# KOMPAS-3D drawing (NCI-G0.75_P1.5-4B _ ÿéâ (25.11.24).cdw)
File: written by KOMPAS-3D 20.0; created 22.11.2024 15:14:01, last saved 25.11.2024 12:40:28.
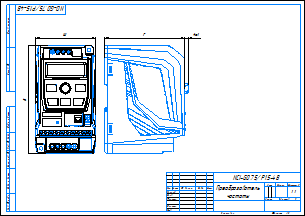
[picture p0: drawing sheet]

Sheet 1: A3, landscape

Document properties: Полное имя файла: P:\INSTART\Технический отдел\ОР\Прочие задачи\КД на номенклатурный ряд\КД на типоразмеры ПЧ\NCI\NCI-G0.75_P1.5-4B _ ШВГ (25.11.24).cdw; Автор: admin

Title block, sheet 1: Наименование: Преобразователь / частоты; designation: NCI-G0.75/P1.5-4B; Количество листов документа: 1; Форматы листов документа: A3; stored path: P:\INSTART\Технический отдел\ОР\Прочие задачи\КД на номенклатурный ряд\КД на типоразмеры ПЧ\NCI\NCI-G0.75_P1.5-4B\NCI-G0.75_P1.5-4B _ Преобразователь частоты.cdw

Views: Вид 1
Dimensions and other numbers on the sheet: 4±1; 1:1; 1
